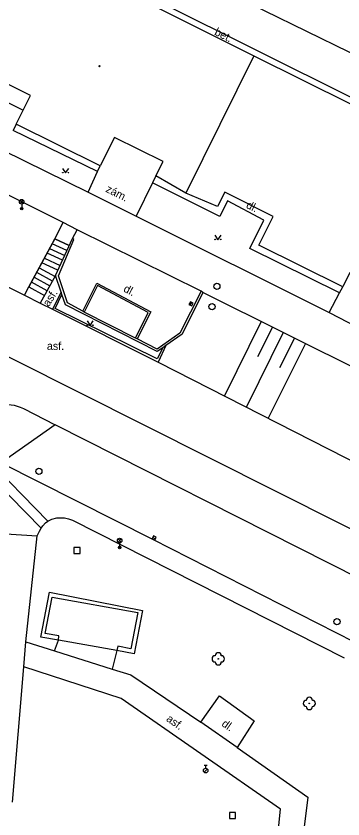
# Model space of a CAD drawing. Extents: x -602419 to -601554, y -1162937 to -1162362.
# Drawn here: x -602108.3 to -602081.8, y -1162633.1 to -1162567.9 of the extents above; entities that cross this region are included whole.
import ezdxf

# ---------------------------------------------------------------- set-up
doc = ezdxf.new("R2010")
doc.units = 0
doc.layers.add('Podklad', color=7, linetype='Continuous')

msp = doc.modelspace()

# ---------------------------------------------------------------- linework, layer by layer
at = {"layer": 'Podklad'}
for p, q in [((-602108.0225, -1162583.13), (-602107.7575, -1162582.865)), ((-602108.0225, -1162582.865), (-602107.7575, -1162583.13)), ((-602107.89, -1162583.185), (-602107.89, -1162583.56)), ((-602094.1884, -1162591.3905), (-602094.0716, -1162591.1695)), ((-602100.0625, -1162610.64), (-602099.7975, -1162610.375)), ((-602100.0625, -1162610.375), (-602099.7975, -1162610.64)), ((-602099.93, -1162610.695), (-602099.93, -1162611.07)), ((-602097.2423, -1162610.2451), (-602097.0177, -1162610.3549)), ((-602093.069, -1162629.316), (-602092.804, -1162629.051)), ((-602093.065, -1162628.7425), (-602092.815, -1162628.7425)), ((-602092.94, -1162628.9925), (-602092.94, -1162628.7425))]:
    msp.add_line(p, q, dxfattribs=at)
for points in [[(-602096.62, -1162566.82), (-602095.06, -1162564.09), (-602077.86, -1162572.5), (-602079.42, -1162575.38)], [(-602080.89, -1162574.65), (-602096.62, -1162566.82)], [(-602096.89, -1162567.23), (-602089.03, -1162571.15)], [(-602104.53, -1162584.69), (-602123.34, -1162575.32), (-602137.52, -1162568.21), (-602137.77, -1162568.67)], [(-602089.03, -1162571.15), (-602094.54, -1162582.3)], [(-602089.03, -1162571.15), (-602081.11, -1162575.08)], [(-602107.18, -1162574.38), (-602111.12, -1162572.43)], [(-602111.7, -1162573.6), (-602107.76, -1162575.56)], [(-602107.76, -1162575.56), (-602107.18, -1162574.38)], [(-602108.33, -1162576.71), (-602107.76, -1162575.56)], [(-602108.33, -1162576.71), (-602108.58, -1162577.2)], [(-602101.52, -1162580.09), (-602108.33, -1162576.71)], [(-602101.73, -1162580.55), (-602108.58, -1162577.2)], [(-602100.34, -1162577.77), (-602101.52, -1162580.09)], [(-602096.4, -1162579.73), (-602100.34, -1162577.77)], [(-602109.42, -1162578.8), (-602102.5, -1162582.23)], [(-602101.73, -1162580.55), (-602101.52, -1162580.09)], [(-602096.98, -1162580.9), (-602096.4, -1162579.73)], [(-602127.46, -1162580.68), (-602121.52, -1162583.69), (-602107.67, -1162590.57)], [(-602104.57, -1162580.2849), (-602104.32, -1162580.6599), (-602104.07, -1162580.2849)], [(-602102.5, -1162582.23), (-602101.73, -1162580.55)], [(-602097.27, -1162581.4699), (-602098.6, -1162584.18)], [(-602096.98, -1162580.9), (-602097.27, -1162581.4699)], [(-602082.06, -1162590.4), (-602089.34, -1162586.78), (-602088.21, -1162584.49), (-602091.17, -1162582.92), (-602091.78, -1162584.19), (-602097.27, -1162581.4699)], [(-602094.54, -1162582.3), (-602096.98, -1162580.9)], [(-602102.5, -1162582.23), (-602098.6, -1162584.18)], [(-602091.9699, -1162583.39), (-602094.54, -1162582.3)], [(-602091.39, -1162582.23), (-602091.9699, -1162583.39)], [(-602087.45, -1162584.19), (-602091.39, -1162582.23)], [(-602105.2, -1162586.02), (-602104.53, -1162584.69)], [(-602103.38, -1162585.27), (-602104.53, -1162584.69)], [(-602098.6, -1162584.18), (-602082.9099, -1162591.98)], [(-602088.61, -1162586.51), (-602087.45, -1162584.19)], [(-602129.79, -1162585.13), (-602076.67, -1162611.8)], [(-602103.77, -1162585.9699), (-602103.38, -1162585.27)], [(-602093.3, -1162590.26), (-602103.38, -1162585.27)], [(-602105.2, -1162586.02), (-602107.3, -1162589.9099)], [(-602107.3, -1162589.9099), (-602105.2, -1162586.02)], [(-602104.0326, -1162586.5487), (-602105.2, -1162586.02)], [(-602105.2, -1162586.02), (-602104.03, -1162586.55)], [(-602105.14, -1162588.99), (-602103.77, -1162585.9699)], [(-602102.93, -1162591.89), (-602104.18, -1162591.21), (-602104.9099, -1162589), (-602103.64, -1162586.06), (-602103.77, -1162585.9699)], [(-602092.19, -1162585.705), (-602091.94, -1162586.08), (-602091.69, -1162585.705)], [(-602104.21, -1162586.95), (-602105.4099, -1162586.4099)], [(-602081.8, -1162589.9), (-602088.61, -1162586.51)], [(-602104.58, -1162587.75), (-602105.83, -1162587.18)], [(-602105.62, -1162586.8), (-602104.39, -1162587.35)], [(-602104.94, -1162588.56), (-602106.25, -1162587.96)], [(-602106.04, -1162587.57), (-602104.76, -1162588.1599)], [(-602106.46, -1162588.35), (-602105.18, -1162589.06)], [(-602106.88, -1162589.13), (-602105.6, -1162589.83)], [(-602105.39, -1162589.45), (-602106.67, -1162588.74)], [(-602105.14, -1162588.99), (-602106.38, -1162591.2199)], [(-602104.68, -1162590.34), (-602105.14, -1162588.99)], [(-602081.2199, -1162588.74), (-602081.8, -1162589.9)], [(-602107.67, -1162590.57), (-602107.3, -1162589.9099)], [(-602107.3, -1162589.9099), (-602106.0382, -1162590.6053)], [(-602107.3, -1162589.9099), (-602106.03, -1162590.61)], [(-602105.82, -1162590.2199), (-602107.09, -1162589.52)], [(-602102.93, -1162591.89), (-602101.79, -1162589.6), (-602097.4, -1162591.93), (-602098.51, -1162594.14)], [(-602098.65, -1162594.07), (-602097.6, -1162591.99), (-602101.7199, -1162589.8), (-602102.8, -1162591.96)], [(-602082.06, -1162590.4), (-602081.8, -1162589.9)], [(-602107.67, -1162590.57), (-602106.38, -1162591.2199)], [(-602104.68, -1162590.34), (-602105.38, -1162591.7199)], [(-602096.43, -1162594.85), (-602096.89, -1162595.76), (-602105.18, -1162591.67), (-602104.62, -1162590.54)], [(-602104.62, -1162590.54), (-602104.68, -1162590.34)], [(-602104.34, -1162591.36), (-602104.62, -1162590.54)], [(-602093.3, -1162590.26), (-602095.04, -1162593.68), (-602096.87, -1162594.96), (-602098.51, -1162594.14)], [(-602093.18, -1162590.36), (-602094.85, -1162593.75)], [(-602093.18, -1162590.36), (-602093.3, -1162590.26)], [(-602076.02, -1162606.6), (-602075.79, -1162606.15), (-602074.32, -1162603.07), (-602073.86, -1162602.17), (-602073.24, -1162600.93), (-602073, -1162600.4099), (-602093.18, -1162590.36)], [(-602082.9099, -1162591.98), (-602082.06, -1162590.4)], [(-602106.38, -1162591.2199), (-602105.38, -1162591.7199)], [(-602105.38, -1162591.7199), (-602096.79, -1162596.01)], [(-602096.87, -1162595.1599), (-602104.34, -1162591.36)], [(-602102.8, -1162591.96), (-602102.93, -1162591.89)], [(-602098.65, -1162594.07), (-602102.8, -1162591.96)], [(-602082.9099, -1162591.98), (-602079.19, -1162593.9099)], [(-602102.58, -1162592.675), (-602102.33, -1162593.05), (-602102.08, -1162592.675)], [(-602088.42, -1162592.73), (-602091.4099, -1162598.75)], [(-602087.52, -1162593.18), (-602088.73, -1162595.59)], [(-602094.85, -1162593.75), (-602096.17, -1162594.6599)], [(-602086.63, -1162593.62), (-602089.63, -1162599.6599)], [(-602098.51, -1162594.14), (-602098.65, -1162594.07)], [(-602084.84, -1162594.51), (-602087.85, -1162600.57)], [(-602085.73, -1162594.07), (-602086.94, -1162596.49)], [(-602096.43, -1162594.85), (-602096.87, -1162595.1599)], [(-602096.17, -1162594.6599), (-602096.79, -1162596.01)], [(-602096.17, -1162594.6599), (-602096.43, -1162594.85)], [(-602096.79, -1162596.01), (-602076.02, -1162606.6)], [(-602112.99, -1162601.53), (-602112.67, -1162601.04), (-602112.11, -1162600.45), (-602111.45, -1162599.99), (-602110.7, -1162599.65), (-602109.9, -1162599.4699), (-602109.2, -1162599.44), (-602108.51, -1162599.52), (-602108.02, -1162599.67), (-602107.73, -1162599.79)], [(-602107.73, -1162599.79), (-602105.17, -1162601.12), (-602109.56, -1162604.2), (-602097.25, -1162610.4), (-602080.87, -1162618.73), (-602065.2199, -1162626.65), (-602060.59, -1162623.63), (-602057.9, -1162625)], [(-602112.99, -1162601.53), (-602112.52, -1162601.71), (-602112.81, -1162602.7), (-602110.92, -1162603.68), (-602105.76, -1162608.92)], [(-602060.59, -1162623.63), (-602105.17, -1162601.12)], [(-602113.48, -1162604.51), (-602112.95, -1162604.52), (-602112.88, -1162603.58), (-602111.39, -1162604.32), (-602106.3, -1162609.49)], [(-602105.76, -1162608.92), (-602105.44, -1162608.77), (-602105.03, -1162608.67), (-602104.77, -1162608.65), (-602104.4, -1162608.6599), (-602104.09, -1162608.73), (-602103.77, -1162608.85)], [(-602103.77, -1162608.85), (-602081.69, -1162620.03)], [(-602106.62, -1162610.11), (-602106.56, -1162609.95), (-602106.45, -1162609.74), (-602106.3, -1162609.49)], [(-602106.3, -1162609.49), (-602106.17, -1162609.32), (-602105.96, -1162609.08), (-602105.76, -1162608.92)], [(-602109.19, -1162609.95), (-602106.62, -1162610.11)], [(-602107.56, -1162618.73), (-602106.62, -1162610.11)], [(-602106.33, -1162618.34), (-602105.64, -1162614.69)], [(-602105.64, -1162614.69), (-602098.08, -1162616.18)], [(-602105.9699, -1162618.04), (-602105.4099, -1162615.09)], [(-602105.4099, -1162615.09), (-602098.45, -1162616.36)], [(-602098.45, -1162616.36), (-602099.02, -1162619.3)], [(-602098.08, -1162616.18), (-602098.76, -1162619.7)], [(-602104.9, -1162618.6), (-602106.33, -1162618.34)], [(-602104.87, -1162618.25), (-602105.9699, -1162618.04)], [(-602105.23, -1162619.46), (-602104.9, -1162618.6)], [(-602104.9, -1162618.6), (-602104.87, -1162618.25)], [(-602100.17, -1162619.44), (-602104.9, -1162618.6)], [(-602107.7199, -1162620.77), (-602107.56, -1162618.73)], [(-602107.56, -1162618.73), (-602105.23, -1162619.46)], [(-602100.08, -1162619.08), (-602100.17, -1162619.44)], [(-602099.02, -1162619.3), (-602100.08, -1162619.08)], [(-602105.23, -1162619.46), (-602100.53, -1162620.95)], [(-602100.17, -1162619.44), (-602100.53, -1162620.95)], [(-602098.76, -1162619.7), (-602100.17, -1162619.44)], [(-602108.64, -1162631.74), (-602107.7199, -1162620.77)], [(-602099.81, -1162623.32), (-602107.7199, -1162620.77)], [(-602100.53, -1162620.95), (-602099.01, -1162621.4)], [(-602099.01, -1162621.4), (-602093.33, -1162625.24)], [(-602093.33, -1162625.24), (-602091.82, -1162623.11)], [(-602091.82, -1162623.11), (-602089, -1162625.15), (-602090.38, -1162627.32)], [(-602086.86, -1162632.32), (-602099.81, -1162623.32)], [(-602090.38, -1162627.32), (-602093.33, -1162625.24)], [(-602090.38, -1162627.32), (-602084.63, -1162631.33)], [(-602084.63, -1162631.33), (-602085.48, -1162638.07)], [(-602087.13, -1162634.9699), (-602086.86, -1162632.32)]]:
    msp.add_lwpolyline(points, dxfattribs=at)
for points in [[(-602094.0779, -1162591.4489), (-602093.9611, -1162591.2279), (-602094.1821, -1162591.1111), (-602094.2989, -1162591.3321)], [(-602097.2972, -1162610.3574), (-602097.0726, -1162610.4672), (-602096.9628, -1162610.2426), (-602097.1874, -1162610.1328)], [(-602103.65, -1162611.57), (-602103.15, -1162611.57), (-602103.15, -1162611.07), (-602103.65, -1162611.07)], [(-602091.01, -1162633.08), (-602090.51, -1162633.08), (-602090.51, -1162632.58), (-602091.01, -1162632.58)]]:
    msp.add_lwpolyline(points, close=True, dxfattribs=at)
for centre, radius in [((-602101.57, -1162571.99), 0.045), ((-602101.57, -1162571.99), 0.0199), ((-602104.5451, -1162580.6348), 0.025), ((-602104.0954, -1162580.6348), 0.025), ((-602107.89, -1162582.9975), 0.1875), ((-602107.89, -1162583.56), 0.1), ((-602107.89, -1162583.56), 0.0723), ((-602107.89, -1162583.56), 0.0438), ((-602092.1651, -1162586.0549), 0.025), ((-602091.7154, -1162586.0549), 0.025), ((-602092.03, -1162589.86), 0.25), ((-602092.42, -1162591.51), 0.25), ((-602102.5551, -1162593.0249), 0.025), ((-602102.1054, -1162593.0249), 0.025), ((-602106.49, -1162604.89), 0.25), ((-602099.93, -1162610.5075), 0.1875), ((-602099.93, -1162611.07), 0.1), ((-602099.93, -1162611.07), 0.0723), ((-602099.93, -1162611.07), 0.0438), ((-602082.27, -1162617.09), 0.25), ((-602091.92, -1162620.11), 0.025), ((-602084.52, -1162623.73), 0.025), ((-602092.94, -1162629.18), 0.1875)]:
    msp.add_circle(centre, radius, dxfattribs=at)
for centre, start, end in [((-602092.17, -1162620.11), 90, 270), ((-602091.92, -1162619.86), 0, 180), ((-602091.67, -1162620.11), 270, 90), ((-602091.92, -1162620.36), 180, 0), ((-602084.52, -1162623.48), 0, 180), ((-602084.77, -1162623.73), 90, 270), ((-602084.27, -1162623.73), 270, 90), ((-602084.52, -1162623.98), 180, 0)]:
    msp.add_arc(centre, 0.25, start, end, dxfattribs=at)

# ---------------------------------------------------------------- texts
for s, rotation, p in [('bet.', 333.57, (-602092.28, -1162569.42)), (' zám.', 333.43, (-602101.34, -1162582.06)), ('dl.', 333.82, (-602089.71, -1162583.4699)), ('dl.', 332.04, (-602099.68, -1162590.25)), ('asf.', 57.22, (-602105.69, -1162591.56)), ('asf.', 324.81, (-602096.2, -1162625.11)), ('dl.', 324.81, (-602091.7, -1162625.51))]:
    msp.add_text(s, height=0.65, rotation=rotation, dxfattribs=at).set_placement(p)
msp.add_text('asf.', height=0.65, dxfattribs=at).set_placement((-602105.84, -1162595.03))

doc.saveas('drawing.dxf')
